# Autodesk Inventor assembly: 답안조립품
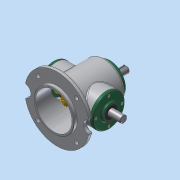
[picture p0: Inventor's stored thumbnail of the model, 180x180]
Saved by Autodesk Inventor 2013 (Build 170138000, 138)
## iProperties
Created: 2018-04
Part Number: 답안조립품
Document SubType Name: Assembly
Designer: dgall
Author: dgall
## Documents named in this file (16)
- C:\Users\dgall\Desktop\480407V1026\답안조립품.iam
- C:\Users\dgall\Desktop\480407V1026\본체.ipt
- C:\Users\dgall\Desktop\480407V1026\메인 베벨기어.ipt
- C:\Users\dgall\Desktop\480407V1026\메인 축.ipt
- 메인 축.ipt
- C:\Users\dgall\Desktop\480407V1026\베어링 6203.ipt
- C:\Users\dgall\Desktop\480407V1026\오일 실.ipt
- 오일 실.ipt
- C:\Users\dgall\Desktop\480407V1026\커버.ipt
- C:\Users\dgall\Desktop\480407V1026\키 5x5.ipt
- C:\Users\dgall\Desktop\480407V1026\서브 베벨기어.ipt
- C:\Users\dgall\Desktop\480407V1026\서브 축.ipt
- 서브 축.ipt
- C:\Users\dgall\Desktop\480407V1026\키 4x4.ipt
- C:\Users\dgall\Desktop\480407V1026\볼트 M4.ipt
- 볼트 M4.ipt
